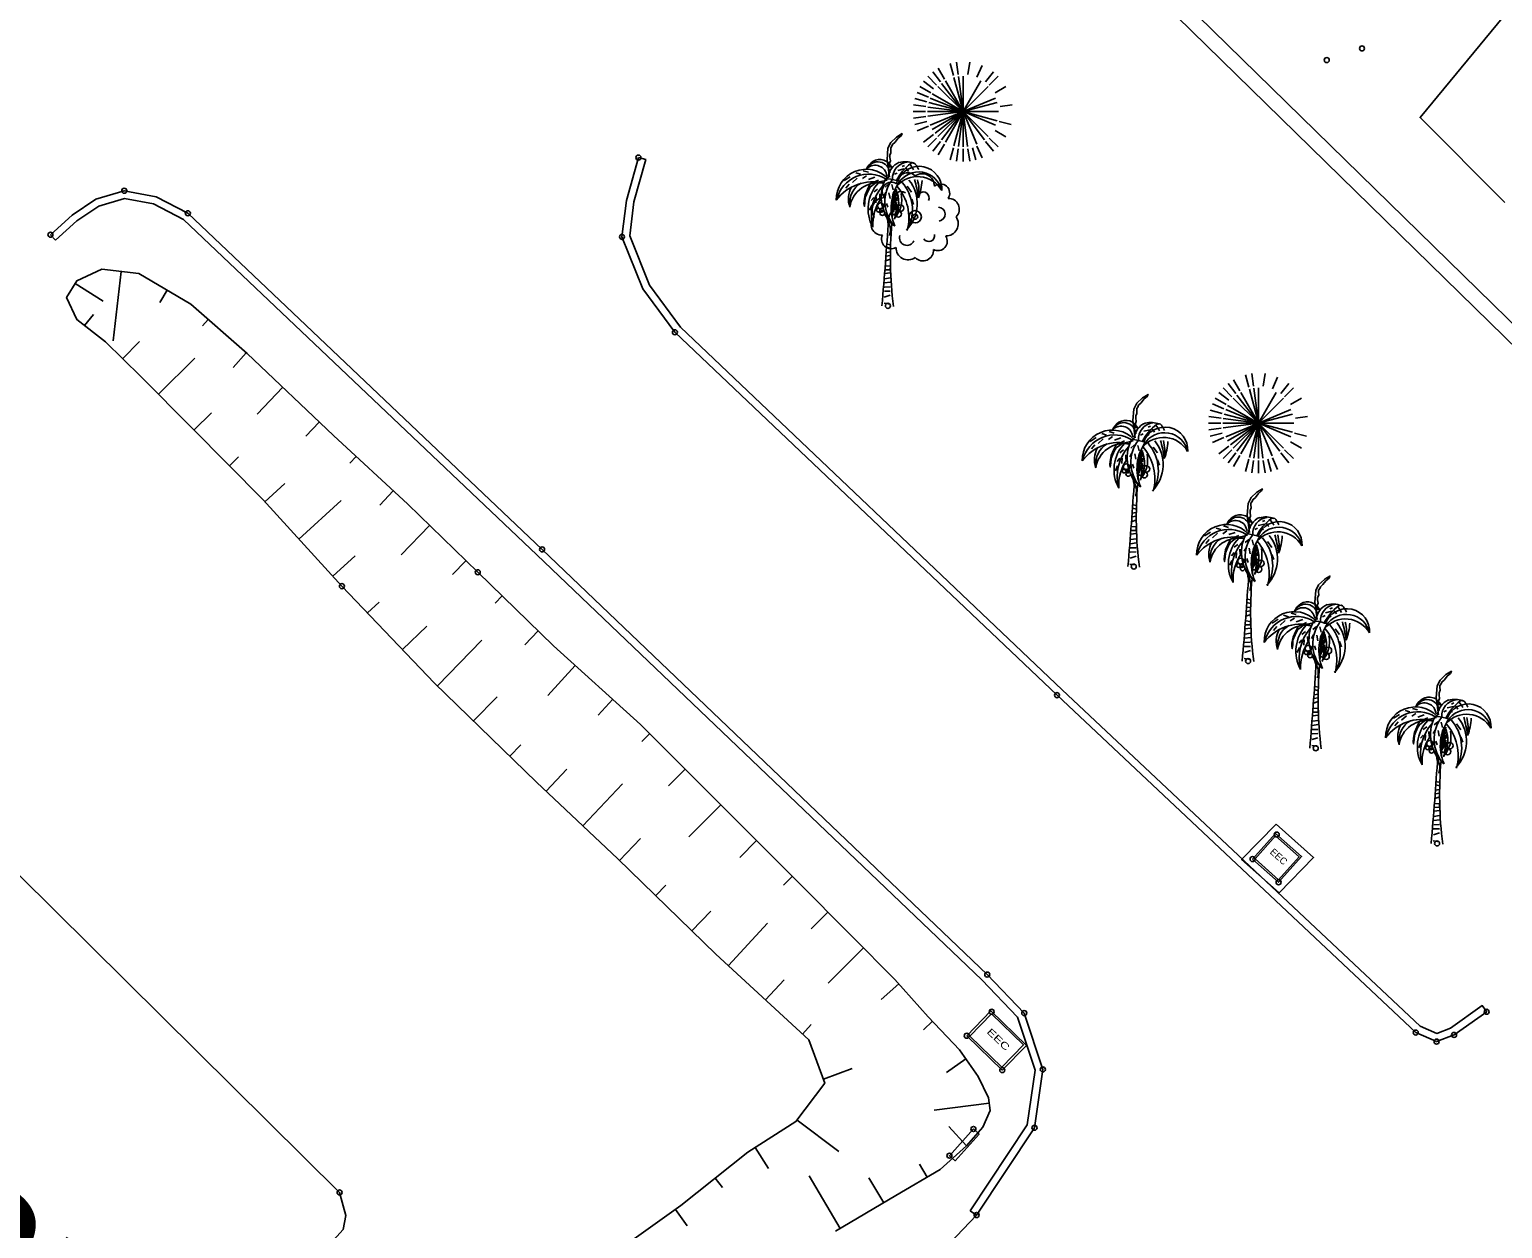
# Model space of a CAD drawing. Extents: x 344013 to 344423, y 298505 to 298795.
# Drawn here: x 344193.18 to 344222.37, y 298722.16 to 298745.94 of the extents above; entities that cross this region are included whole.
import ezdxf

# ---------------------------------------------------------------- set-up
doc = ezdxf.new("R2010")
doc.units = 0
for name, color, linetype in [('Default', 7, 'Continuous'), ('GO_MUR', 7, 'Continuous'), ('PS_BOLT', 7, 'Continuous'), ('PS_CONST', 7, 'Continuous'), ('PS_SOLID', 7, 'Continuous'), ('RES_ELECTRICITE', 7, 'Continuous'), ('TOPO_POINT', 7, 'Continuous'), ('TOPO_TALUS-TERRAIN NATUREL', 7, 'Continuous'), ('VOIRIE_BORDURE', 7, 'Continuous'), ('VOIRIE_ESPACE VERT', 7, 'Continuous')]:
    doc.layers.add(name, color=color, linetype=linetype)

# ---------------------------------------------------------------- blocks, each defined once
blk = doc.blocks.new('RES_ELECTRICITE')
at = {"layer": 'RES_ELECTRICITE'}
for points in [[(0, 0), (0, 1), (1, 1), (1, 0)], [(0.05, 0.05), (0.05, 0.95), (0.95, 0.95), (0.95, 0.05)]]:
    blk.add_lwpolyline(points, close=True, dxfattribs=at)
blk.add_text('EEC', height=0.2, dxfattribs=at).set_placement((0.237, 0.46))
blk = doc.blocks.new('POINT_DISPLAY')
at = {"layer": 'Default'}
blk.add_circle((0, 0), 0.05, dxfattribs=at)
blk = doc.blocks.new('COCO')
at = {"layer": 'Default'}
for p, q in [((-0.026, 1.226), (0.061, 1.212)), ((-0.046, 0.891), (0.052, 0.927)), ((0.054, 0.998), (-0.041, 0.985)), ((-0.037, 1.06), (0.056, 1.071)), ((0.058, 1.14), (-0.03, 1.162)), ((0.047, 0.655), (-0.058, 0.642)), ((-0.068, 0.371), (0.045, 0.374)), ((0.045, 0.47), (-0.065, 0.453)), ((-0.062, 0.537), (0.046, 0.552)), ((0.046, 0.033), (-0.076, 0.051)), ((-0.073, 0.17), (0.045, 0.209)), ((0.045, 0.292), (-0.07, 0.288))]:
    blk.add_line(p, q, dxfattribs=at)
for points in [[(0.029, 2.551), (-0.016, 2.896), (0.002, 3.125), (0.059, 3.241), (0.173, 3.348), (0.189, 3.356), (0.282, 3.415), (0.266, 3.373), (0.2, 3.318), (0.143, 3.247), (0.093, 3.2), (0.081, 3.165), (0.057, 3.133), (0.057, 3.099), (0.06, 3.037), (0.039, 2.989), (0.039, 2.944), (0.049, 2.877), (0.037, 2.841), (0.013, 2.736)], [(-0.636, 2.639), (-0.541, 2.608)], [(-0.487, 2.68), (-0.386, 2.65)], [(0.013, 2.736), (0.036, 2.813), (0.046, 2.746)], [(0.133, 2.608), (0.185, 2.634)], [(0.196, 2.687), (0.323, 2.715)], [(0.283, 2.765), (0.331, 2.786)], [(-0.746, 2.559), (-0.864, 2.483)], [(-0.77, 2.413), (-0.836, 2.333)], [(-0.607, 2.534), (-0.704, 2.443)], [(-0.421, 2.58), (-0.503, 2.523)], [(-0.183, 2.493), (-0.348, 2.417), (-0.401, 2.307), (-0.448, 2.203), (-0.471, 2.086), (-0.474, 2.023), (-0.466, 1.973), (-0.455, 2.054), (-0.451, 2.146), (-0.387, 2.292), (-0.351, 2.354), (-0.284, 2.404), (-0.233, 2.445), (-0.012, 2.495)], [(-0.256, 2.553), (-0.385, 2.508)], [(0.015, 2.414), (-0.056, 2.352)], [(0.081, 2.404), (0.106, 2.299)], [(0.385, 2.37), (0.469, 2.254)], [(-0.276, 2.151), (-0.329, 2.086)], [(-0.203, 2.314), (-0.274, 2.258)], [(-0.23, 2.152), (-0.237, 2.043)], [(-0.161, 2.218), (-0.158, 2.122)], [(-0.04, 2.247), (-0.081, 2.179)], [(0.022, 2.24), (0.043, 2.13)], [(0.473, 2.115), (0.509, 2.012)], [(-0.321, 1.997), (-0.364, 1.9)], [(-0.059, 2.024), (-0.083, 1.998)], [(-0.025, 2.032), (0.002, 1.954)], [(-0.055, 0.716), (0.048, 0.717), (0.049, 0.787), (-0.051, 0.795)]]:
    blk.add_lwpolyline(points, dxfattribs=at)
for centre, radius in [((-0.187, 1.897), 0.0384), ((-0.144, 1.978), 0.0616), ((-0.124, 1.896), 0.0376), ((-0.11, 1.84), 0.0471), ((0.134, 1.862), 0.0549), ((0.208, 1.822), 0.0626), ((0.254, 1.938), 0.0628)]:
    blk.add_circle(centre, radius, dxfattribs=at)
for centre, radius, start, end in [((-0.427, 2.113), 0.595, 43.6121, 181.4625), ((-0.123, 2.59), 0.323, 122.3475, 158.7636), ((-0.199, 2.618), 0.238, 4.5218, 154.101), ((-0.252, 2.556), 0.231, 4.2441, 134.2103), ((-0.16, 2.647), 0.255, 21.0861, 122.3475), ((0.376, 2.508), 0.372, 113.7681, 175.3309), ((0.376, 2.508), 0.372, 113.7681, 175.3309), ((0.418, 2.527), 0.326, 97.1248, 183.9512), ((1.025, 2.053), 0.958, 126.6858, 153.1664), ((0.618, 2.316), 0.451, 356.1627, 159.0009), ((0.609, 2.187), 0.468, 12.1077, 148.3146), ((0.344, 2.407), 0.451, 69.0817, 104.862), ((-0.157, 2.027), 0.74, 51.2475, 54.5217), ((-1.005, 1.577), 1.786, 37.5668, 40.5156), ((-0.254, 2.28), 0.869, 28.4725, 37.0965), ((0.493, 2.767), 0.0679, 35.3205, 126.6858), ((-0.054, 2.379), 0.738, 25.8194, 35.3205), ((-0.291, 1.543), 0.918, 76.7389, 142.8025), ((-0.38, 1.964), 0.648, 57.9192, 166.6201), ((-0.3, 2.12), 0.482, 151.1331, 199.5942), ((-0.196, 1.874), 0.565, 78.514, 171.3504), ((-0.32, 2.055), 0.433, 119.0834, 188.7621), ((0.362, 1.922), 0.754, 136.7113, 208.8221), ((0.551, 1.79), 0.879, 137.733, 194.3716), ((0.62, 2.159), 0.753, 153.0868, 230.1124), ((0.659, 2.068), 0.718, 142.3554, 222.2794), ((-0.007, 2.465), 0.0563, 81.7475, 144.3035), ((-0.189, 1.21), 1.324, 71.3715, 81.7475), ((0.294, 2.595), 0.256, 198.6765, 199.7627), ((0.963, 1.939), 0.9, 143.9866, 203.4288), ((0.59, 2.015), 0.548, 29.5654, 139.3517), ((-0.543, 1.744), 0.96, 344.8781, 41.1461), ((-0.341, 1.9), 0.828, 46.9767, 50.1231), ((-0.341, 1.9), 0.828, 334.0687, 41.194), ((-0.157, 2.027), 0.74, 315.1472, 39.0239), ((-1.704, 1.849), 2.327, 7.5978, 16.3666), ((-0.254, 2.28), 0.869, 350.8883, 14.7063), ((-0.482, 2.552), 1.161, 339.3597, 356.5925), ((0.649, 1.599), 0.949, 145.5146, 182.4528), ((0.544, 1.816), 0.474, 137.1953, 172.8987), ((0.308, 2.014), 0.226, 121.4297, 182.29), ((27.302, 0.106), 27.266, 175.4791, 176.5597), ((0.311, 2.152), 0.219, 141.856, 191.5175), ((0.372, 1.847), 0.277, 133.5956, 173.487), ((0.242, 1.964), 0.147, 110.9727, 165.9756), ((0.404, 1.878), 0.354, 125.0585, 146.3893), ((0.398, 2.098), 0.301, 136.4569, 162.0685), ((0.357, 2.084), 0.244, 133.1184, 172.7534), ((-0.759, 1.958), 0.922, 344.8505, 15.8988), ((-0.404, 2.045), 0.619, 329.4666, 26.6793), ((-0.289, 2.11), 0.564, 317.8279, 12.3386), ((-0.279, 1.637), 0.281, 2.1499, 36.6325), ((0.808, 1.542), 0.777, 142.2358, 156.28), ((-85.428, 7.294), 85.622, 355.11326, 356.26352), ((-0.265, 1.505), 0.316, 339.9997, 25.7228), ((0.199, 1.66), 0.176, 166.9443, 185.5966)]:
    blk.add_arc(centre, radius, start, end, dxfattribs=at)
blk.add_ellipse((27.425, 0.272), major_axis=(-27.371, 0.966), ratio=0.529859, start_param=6.255729, end_param=6.369141, dxfattribs=at)
blk = doc.blocks.new('ARB1')
at = {"layer": 'Default'}
blk.add_circle((0, 0), 0.122, dxfattribs=at)
for centre, radius, start, end in [((-0.471, 0.503), 0.183, 53.9554, 222.2066), ((-0.153, 0.664), 0.211, 43.6925, 183.5969), ((0.139, 0.613), 0.241, 358.4583, 125.1928), ((0.501, 0.468), 0.183, 325.1444, 131.0175), ((-0.613, 0.139), 0.241, 88.4583, 215.1928), ((-0.276, 0.37), 0.134, 52.4396, 209.5496), ((0.164, 0.38), 0.112, 330.5895, 133.7127), ((0.664, 0.153), 0.211, 313.6925, 93.5969), ((-0.373, -0.024), 0.149, 103.7092, 242.3465), ((0.458, 0.052), 0.137, 276.6214, 88.967), ((0.613, -0.139), 0.241, 268.4583, 35.1928), ((-0.664, -0.153), 0.211, 133.6925, 273.5969), ((-0.478, -0.443), 0.19, 155.2243, 300.9377), ((-0.163, -0.42), 0.148, 159.5371, 338.1663), ((0.271, -0.38), 0.112, 210.5895, 13.7127), ((0.448, -0.483), 0.188, 243.1323, 33.0297), ((-0.139, -0.613), 0.241, 178.4583, 305.1928), ((0.153, -0.664), 0.211, 223.6925, 3.5969)]:
    blk.add_arc(centre, radius, start, end, dxfattribs=at)
blk = doc.blocks.new('ARB2')
at = {"layer": 'Default'}
for p, q in [((-0.181, 0.716), (-0.244, 0.956)), ((-0.088, 0.736), (-0.119, 0.983)), ((0.106, 0.736), (0.144, 0.983)), ((0.287, 0.684), (0.388, 0.914)), ((-0.575, 0.453), (-0.775, 0.605)), ((-0.513, 0.525), (-0.688, 0.702)), ((-0.438, 0.589), (-0.588, 0.786)), ((-0.356, 0.642), (-0.481, 0.858)), ((0.456, 0.589), (0.612, 0.786)), ((0.531, 0.525), (0.706, 0.702)), ((-0.675, 0.286), (-0.9, 0.381)), ((-0.631, 0.373), (-0.844, 0.497)), ((0.65, 0.373), (0.862, 0.497)), ((-0.731, 0), (-0.981, 0)), ((-0.725, 0.1), (-0.969, 0.133)), ((-0.706, 0.195), (-0.944, 0.259)), ((0.744, 0.1), (0.987, 0.133)), ((-0.725, -0.1), (-0.969, -0.133)), ((-0.706, -0.195), (-0.944, -0.259)), ((-0.675, -0.287), (-0.9, -0.383)), ((0.725, -0.195), (0.963, -0.259)), ((-0.575, -0.455), (-0.775, -0.605)), ((-0.513, -0.527), (-0.688, -0.702)), ((0.531, -0.527), (0.706, -0.702)), ((0.65, -0.373), (0.862, -0.498)), ((-0.438, -0.591), (-0.588, -0.787)), ((-0.356, -0.644), (-0.481, -0.859)), ((-0.181, -0.717), (-0.244, -0.956)), ((-0.088, -0.737), (-0.119, -0.983)), ((0.013, -0.741), (0.013, -0.989)), ((0.106, -0.737), (0.144, -0.983)), ((0.2, -0.717), (0.263, -0.956)), ((0.287, -0.686), (0.388, -0.916)), ((0.456, -0.591), (0.612, -0.787))]:
    blk.add_line(p, q, dxfattribs=at)
for points in [[(-0.688, 0.091), (0.013, 0), (-0.338, 0.608)], [(-0.169, 0.677), (0.013, 0), (-0.6, 0.35)], [(0.013, 0.008), (0.013, 0), (-0.081, 0.695)], [(0.362, 0.608), (0.013, 0), (0.013, 0.702)], [(-0.487, 0.495), (0.013, 0), (-0.669, 0.181)], [(-0.419, 0.556), (0.013, 0), (-0.638, 0.269)], [(0.656, 0.269), (0.013, 0), (0.506, 0.495)], [(-0.487, -0.497), (0.013, 0), (-0.694, 0)], [(-0.638, -0.269), (0.013, 0), (-0.688, -0.092)], [(-0.169, -0.678), (0.013, 0), (-0.6, -0.352)], [(-0.544, -0.428), (0.013, 0), (-0.338, -0.608)], [(-0.081, -0.695), (0.013, 0), (-0.419, -0.558)], [(0.013, -0.702), (0.013, 0), (0, 0)], [(0.688, 0.181), (0.013, 0), (0.713, 0)], [(0.438, -0.558), (0.013, 0), (0.656, -0.269)], [(0.506, -0.497), (0.013, 0), (0.688, -0.181)], [(0.1, -0.695), (0.013, 0), (0.281, -0.648)], [(0.019, 0), (0.013, 0), (0.013, -0.009)]]:
    blk.add_lwpolyline(points, dxfattribs=at)

msp = doc.modelspace()

# ---------------------------------------------------------------- linework, layer by layer
at = {"layer": 'GO_MUR'}
msp.add_lwpolyline([(344211.884, 298724.136), (344211.41, 298723.607), (344211.522, 298723.507), (344211.996, 298724.035)], close=True, dxfattribs=at)
at = {"layer": 'PS_BOLT'}
msp.add_lwpolyline([(344217.889, 298730.183), (344217.202, 298729.481), (344217.942, 298728.821), (344218.629, 298729.523)], close=True, dxfattribs=at)
at = {"layer": 'PS_SOLID'}
msp.add_lwpolyline([(344186.775, 298708.762), (344186.137, 298708.472), (344185.611, 298708.543), (344184.558, 298709.458), (344178.763, 298715.051), (344178.45, 298715.571), (344178.356, 298716.027), (344178.695, 298716.632), (344191.505, 298729.761), (344191.946, 298729.981), (344192.26, 298729.87), (344199.324, 298722.877), (344199.449, 298722.421), (344199.394, 298722.145), (344198.827, 298721.518), (344186.775, 298708.762)], dxfattribs=at)
at = {"layer": 'TOPO_TALUS-TERRAIN NATUREL'}
for p, q in [((344194.996, 298741.139), (344194.832, 298739.763)), ((344194.08, 298740.9), (344194.64, 298740.553)), ((344195.904, 298740.768), (344195.76, 298740.524)), ((344194.269, 298740.068), (344194.442, 298740.289)), ((344196.716, 298740.191), (344196.607, 298740.066)), ((344195.022, 298739.412), (344195.358, 298739.755)), ((344195.732, 298738.707), (344196.451, 298739.423)), ((344197.468, 298739.531), (344197.213, 298739.24)), ((344198.195, 298738.844), (344197.69, 298738.312)), ((344196.438, 298737.998), (344196.781, 298738.337)), ((344198.921, 298738.156), (344198.655, 298737.876)), ((344197.14, 298737.286), (344197.321, 298737.465)), ((344199.651, 298737.472), (344199.526, 298737.338)), ((344197.841, 298736.572), (344198.237, 298736.934)), ((344200.384, 298736.792), (344200.122, 298736.509)), ((344198.516, 298735.834), (344199.351, 298736.598)), ((344201.108, 298736.102), (344200.543, 298735.519)), ((344199.19, 298735.096), (344199.631, 298735.499)), ((344201.826, 298735.406), (344201.558, 298735.129)), ((344199.877, 298734.369), (344200.105, 298734.586)), ((344202.544, 298734.709), (344202.403, 298734.563)), ((344200.569, 298733.646), (344201.049, 298734.106)), ((344203.261, 298734.012), (344202.994, 298733.737)), ((344201.262, 298732.925), (344202.143, 298733.831)), ((344203.993, 298733.33), (344203.451, 298732.73)), ((344201.979, 298732.228), (344202.444, 298732.705)), ((344204.736, 298732.66), (344204.45, 298732.344)), ((344205.469, 298731.98), (344205.31, 298731.822)), ((344202.696, 298731.53), (344202.917, 298731.757)), ((344203.416, 298730.836), (344203.829, 298731.273)), ((344206.175, 298731.271), (344205.841, 298730.938)), ((344204.143, 298730.149), (344204.927, 298730.979)), ((344206.881, 298730.563), (344206.248, 298729.932)), ((344204.87, 298729.462), (344205.29, 298729.894)), ((344207.587, 298729.855), (344207.254, 298729.522)), ((344205.588, 298728.765), (344205.787, 298728.97)), ((344208.294, 298729.146), (344208.118, 298728.971)), ((344206.305, 298728.068), (344206.684, 298728.458)), ((344209, 298728.438), (344208.667, 298728.106)), ((344207.028, 298727.377), (344207.807, 298728.218)), ((344209.706, 298727.729), (344209.004, 298727.031)), ((344207.762, 298726.697), (344208.132, 298727.097)), ((344210.407, 298727.016), (344210.057, 298726.704)), ((344211.076, 298726.272), (344210.896, 298726.102)), ((344208.496, 298726.018), (344208.672, 298726.208)), ((344211.738, 298725.526), (344211.354, 298725.258)), ((344208.912, 298725.125), (344209.48, 298725.337)), ((344212.197, 298724.648), (344211.11, 298724.512)), ((344208.392, 298724.314), (344209.219, 298723.69)), ((344211.747, 298723.802), (344211.398, 298724.186)), ((344207.557, 298723.768), (344207.821, 298723.352)), ((344210.969, 298723.18), (344210.815, 298723.441)), ((344206.764, 298723.16), (344206.91, 298722.977)), ((344209.245, 298722.164), (344208.629, 298723.208)), ((344210.107, 298722.673), (344209.814, 298723.168)), ((344205.978, 298722.542), (344206.21, 298722.217))]:
    msp.add_line(p, q, dxfattribs=at)
msp.add_lwpolyline([(344204.792, 298721.692), (344206.083, 298722.617), (344207.415, 298723.677), (344208.367, 298724.282), (344208.943, 298725.043), (344208.621, 298725.903), (344206.781, 298727.605), (344204.835, 298729.496), (344203.225, 298731.016), (344201.206, 298732.979), (344199.369, 298734.901), (344197.806, 298736.61), (344196.401, 298738.036), (344195.38, 298739.061), (344194.68, 298739.746), (344194.115, 298740.188), (344193.911, 298740.628), (344194.116, 298740.958), (344194.612, 298741.185), (344195.344, 298741.098), (344196.374, 298740.49), (344197.489, 298739.513), (344199.203, 298737.889), (344200.672, 298736.525), (344202.062, 298735.177), (344203.561, 298733.72), (344205.29, 298732.159), (344206.617, 298730.828), (344208.376, 298729.064), (344209.475, 298727.961), (344210.331, 298727.102), (344210.991, 298726.362), (344211.611, 298725.708), (344211.979, 298725.18), (344212.183, 298724.755), (344212.215, 298724.503), (344212.073, 298724.173), (344211.749, 298723.804), (344211.229, 298723.332), (344210.347, 298722.815), (344209.151, 298722.109)], dxfattribs=at)
at = {"layer": 'VOIRIE_BORDURE'}
for points in [[(344205.246, 298743.4), (344205.01, 298742.551), (344204.92, 298741.828), (344205.331, 298740.794), (344205.968, 298739.935), (344213.542, 298732.739), (344220.653, 298726.049), (344221.066, 298725.869), (344221.412, 298726.001), (344222.058, 298726.46)], [(344222.058, 298726.46), (344221.971, 298726.582), (344221.341, 298726.135), (344221.07, 298726.031), (344220.737, 298726.176), (344213.645, 298732.848), (344206.08, 298740.035), (344205.463, 298740.868), (344205.074, 298741.848), (344205.157, 298742.521), (344205.391, 298743.36), (344205.246, 298743.4)], [(344211.949, 298722.43), (344213.096, 298724.161), (344213.261, 298725.318), (344212.893, 298726.434), (344212.16, 298727.197), (344203.337, 298735.63), (344196.315, 298742.295), (344195.685, 298742.624), (344195.054, 298742.742), (344194.49, 298742.574), (344194.02, 298742.261), (344193.592, 298741.871)], [(344211.824, 298722.513), (344212.952, 298724.216), (344213.108, 298725.305), (344212.762, 298726.355), (344212.054, 298727.091), (344203.234, 298735.521), (344196.227, 298742.172), (344195.636, 298742.481), (344195.062, 298742.588), (344194.554, 298742.437), (344194.113, 298742.143), (344193.693, 298741.76)], [(344193.592, 298741.871), (344193.693, 298741.76)], [(344211.824, 298722.513), (344211.949, 298722.43)], [(344128.542, 298697.099), (344156.76, 298672.229), (344158.923, 298671.699), (344160.816, 298671.605), (344163.478, 298672.279), (344165.611, 298673.484), (344167.1, 298674.65), (344168.229, 298675.97), (344185.426, 298693.989), (344196.039, 298705.71), (344211.949, 298722.43)]]:
    msp.add_lwpolyline(points, dxfattribs=at)
at = {"layer": 'VOIRIE_ESPACE VERT'}
for points in [[(344228.609, 298733.786), (344215.617, 298746.488), (344237.992, 298769.574), (344251.389, 298756.925), (344242.713, 298747.917), (344242.041, 298748.012), (344241.328, 298747.986), (344240.625, 298747.821), (344240.024, 298747.565), (344239.421, 298747.187), (344239.008, 298746.783), (344238.537, 298746.143), (344238.196, 298745.471), (344238.047, 298744.807), (344237.999, 298744.129), (344238.073, 298743.423)], [(344228.605, 298734.21), (344216.04, 298746.493), (344238.001, 298769.152), (344250.963, 298756.915), (344242.603, 298748.236), (344242.057, 298748.313), (344241.288, 298748.284), (344240.531, 298748.107), (344239.884, 298747.832), (344239.235, 298747.424), (344238.781, 298746.98), (344238.281, 298746.301), (344237.912, 298745.574), (344237.75, 298744.85), (344237.698, 298744.124), (344237.76, 298743.532)]]:
    msp.add_lwpolyline(points, close=True, dxfattribs=at)
msp.add_lwpolyline([(344222.418, 298742.507), (344220.739, 298744.193), (344222.741, 298746.629), (344219.835, 298749.685), (344221.506, 298751.241), (344224.052, 298749.112)], dxfattribs=at)

# ---------------------------------------------------------------- block references
at = {"layer": 'RES_ELECTRICITE'}
for p, xscale, yscale, rotation in [((344217.419, 298729.488), 0.690755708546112, 0.6812524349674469, -41.73561000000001), ((344211.753, 298725.986), 0.981110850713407, 0.6853210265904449, -44.12101746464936)]:
    msp.add_blockref('RES_ELECTRICITE', p, dxfattribs=dict(at, xscale=xscale, yscale=yscale, rotation=rotation))
at = {"layer": 'TOPO_POINT'}
for p in [(344219.587, 298745.565), (344218.889, 298745.333), (344211.669, 298744.312), (344205.246, 298743.4), (344195.054, 298742.742), (344196.315, 298742.295), (344210.731, 298742.226), (344193.592, 298741.871), (344204.92, 298741.828), (344210.19, 298740.46), (344205.968, 298739.935), (344217.523, 298738.133), (344203.337, 298735.63), (344215.064, 298735.288), (344202.062, 298735.177), (344199.369, 298734.901), (344217.33, 298733.415), (344213.542, 298732.739), (344218.669, 298731.687), (344217.896, 298729.975), (344221.076, 298729.798), (344217.419, 298729.488), (344217.935, 298729.028), (344212.16, 298727.197), (344212.247, 298726.462), (344212.893, 298726.434), (344222.058, 298726.46), (344211.753, 298725.986), (344220.653, 298726.049), (344221.412, 298726.001), (344221.066, 298725.869), (344213.261, 298725.318), (344212.458, 298725.303), (344213.096, 298724.161), (344211.884, 298724.136), (344211.41, 298723.607), (344199.324, 298722.877), (344211.949, 298722.43)]:
    msp.add_blockref('POINT_DISPLAY', p, dxfattribs=at)
at = {"layer": 'VOIRIE_ESPACE VERT'}
for name, p in [('ARB2', (344211.669, 298744.312)), ('COCO', (344210.19, 298740.46)), ('ARB1', (344210.731, 298742.226)), ('ARB2', (344217.523, 298738.133)), ('COCO', (344215.064, 298735.288)), ('COCO', (344217.33, 298733.415)), ('COCO', (344218.669, 298731.687)), ('COCO', (344221.076, 298729.798))]:
    msp.add_blockref(name, p, dxfattribs=at)

# ---------------------------------------------------------------- texts
at = {"layer": 'PS_CONST'}
msp.add_text('0067', height=2.9662, rotation=320.3665, dxfattribs=at).set_placement((344186.769, 298724.069))

doc.saveas('drawing.dxf')
